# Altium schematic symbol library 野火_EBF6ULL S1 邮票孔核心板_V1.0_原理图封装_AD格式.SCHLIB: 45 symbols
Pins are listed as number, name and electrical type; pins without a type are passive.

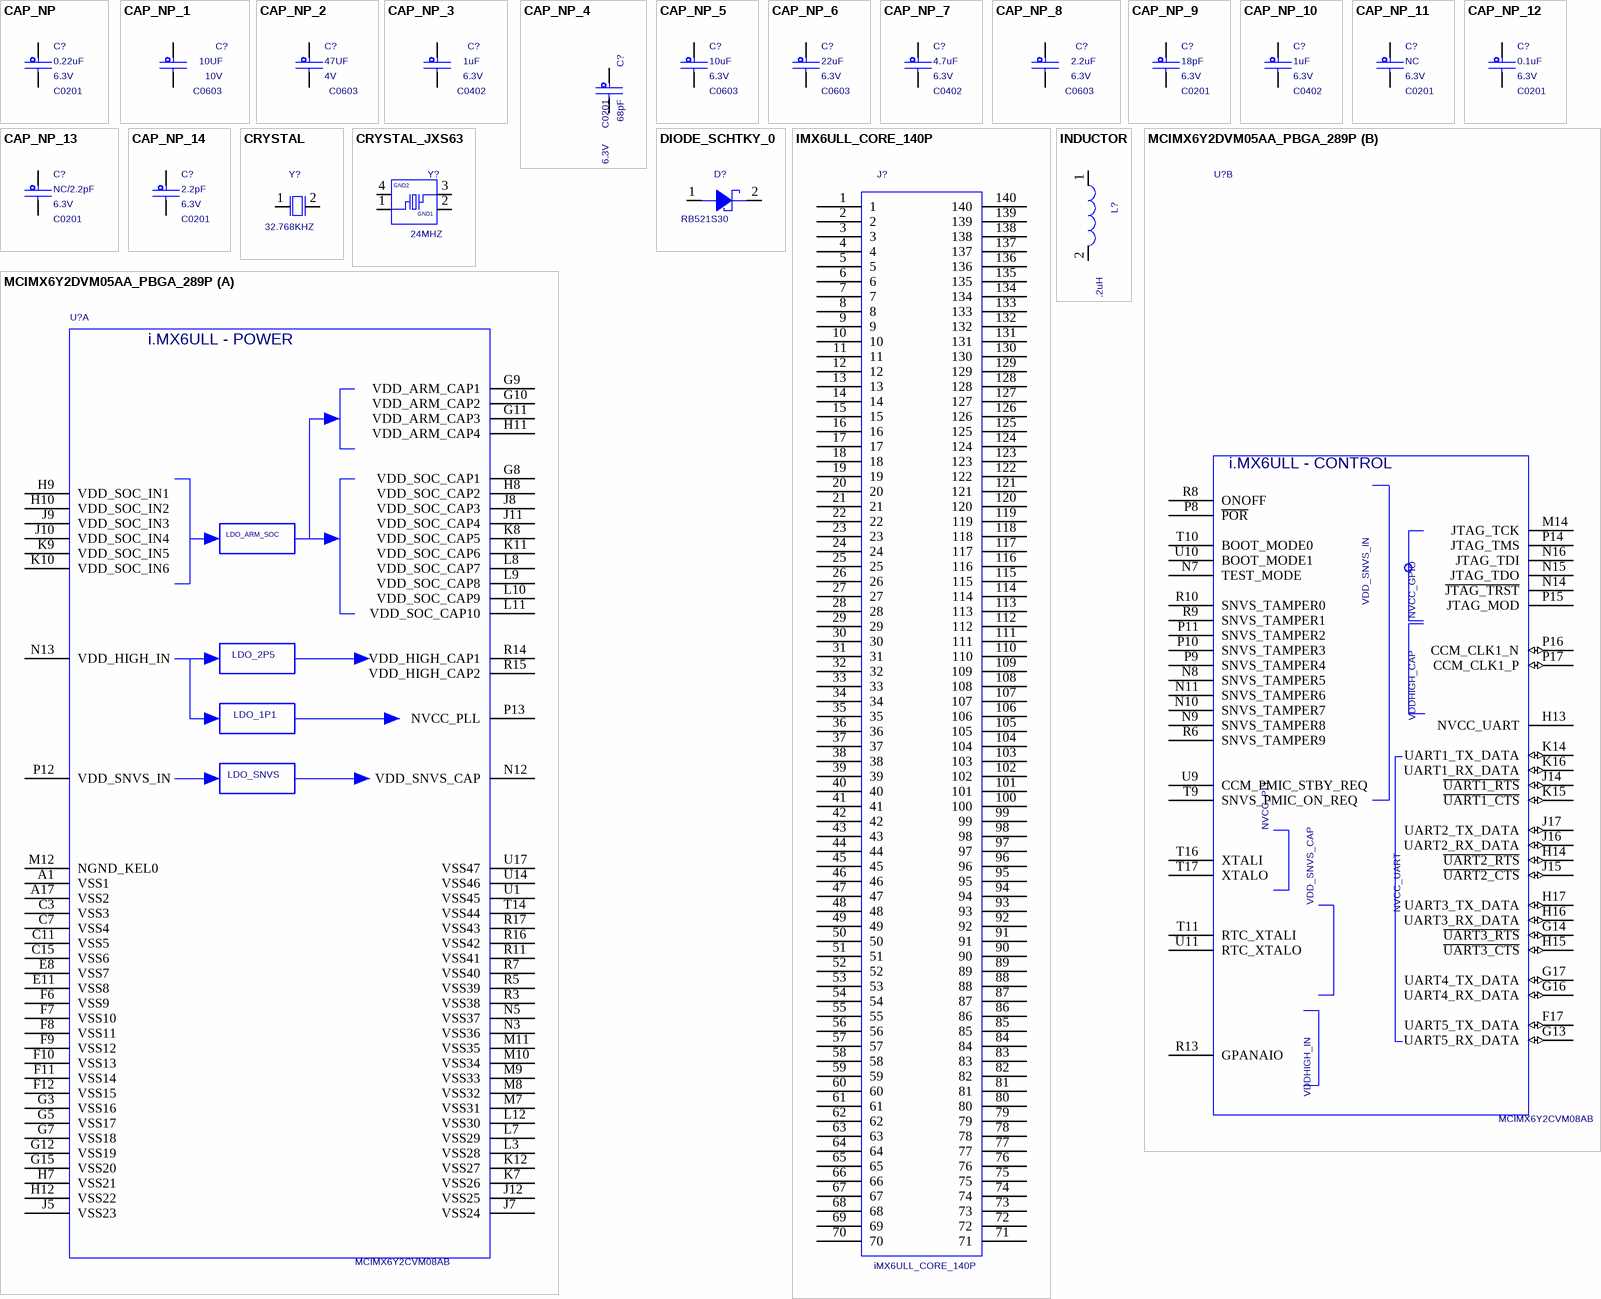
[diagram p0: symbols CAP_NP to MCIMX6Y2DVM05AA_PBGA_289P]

## CAP_NP
designator C?  value 0.22uF  VOLTAGE: 6.3V  PCB DECAL: C0201  (hidden comment: CAP_NP)
CAP CER 0.22UF 6.3V 20% X5R 0402; AGILE_PN: 150-76271; MFG_NAME01: KEMET; MFG_PN01: C0402C224M9PAC; CAD_APPROVED: Yes; FPLIST: CC0402_25,CC0402_HD,0402_CC; Source_Path: Q:\ORCADCIS\SYMBOLS\FCL_CAPACITOR.OLB; CLASS: DISCRETE
footprint C0201
pins: 1, 2

## CAP_NP_1
designator C?, comment value 10UF  PCB DECAL: C0603  voltage_rating: 10V  (hidden comment: CAP_NP)
CAP CER 22UF 6.3V 20% X5R 0603; FPLIST: CC0603_OV,CC0603,0603_CC; CAD_APPROVED: Yes; MFG_PN01: CL10A226MQ8NRNE; MFG_NAME01: Samsung; AGILE_PN: 150-78467; Source_Path: Q:\ORCADCIS\SYMBOLS\FCL_CAPACITOR.OLB; CLASS: DISCRETE
footprint C0603
pins: 1, 2

## CAP_NP_2
designator C?, comment value 47UF  PCB DECAL: C0603  voltage_rating: 4V  (hidden comment: CAP_NP)
CAP CER 22UF 6.3V 20% X5R 0603; AGILE_PN: 150-78467; MFG_NAME01: Samsung; MFG_PN01: CL10A226MQ8NRNE; CAD_APPROVED: Yes; FPLIST: CC0603_OV,CC0603,0603_CC; Source_Path: Q:\ORCADCIS\SYMBOLS\FCL_CAPACITOR.OLB; CLASS: DISCRETE
footprint C0603
pins: 1, 2

## CAP_NP_3
designator C?, comment value 1uF  PCB DECAL: C0402  voltage_rating: 6.3V  (hidden comment: CAP_NP)
CAP CER 22UF 6.3V 20% X5R 0603; FPLIST: CC0603_OV,CC0603,0603_CC; CAD_APPROVED: Yes; MFG_PN01: CL10A226MQ8NRNE; MFG_NAME01: Samsung; AGILE_PN: 150-78467; Source_Path: Q:\ORCADCIS\SYMBOLS\FCL_CAPACITOR.OLB; CLASS: DISCRETE
footprint C0402
pins: 1, 2

## CAP_NP_4
designator C?, comment value 68pF  VOLTAGE: 6.3V  PCB DECAL: C0201  (hidden comment: CAP_NP)
CAP CER 0.22UF 6.3V 20% X5R 0402; FPLIST: CC0402_25,CC0402_HD,0402_CC; CAD_APPROVED: Yes; MFG_PN01: C0402C224M9PAC; MFG_NAME01: KEMET; AGILE_PN: 150-76271; Source_Path: Q:\ORCADCIS\SYMBOLS\FCL_CAPACITOR.OLB; CLASS: DISCRETE
footprint C0201
pins: 1, 2

## CAP_NP_5
designator C?, comment value 10uF  VOLTAGE: 6.3V  PCB DECAL: C0603  (hidden comment: CAP_NP)
CAP CER 0.22UF 6.3V 20% X5R 0402; FPLIST: CC0402_25,CC0402_HD,0402_CC; CAD_APPROVED: Yes; MFG_PN01: C0402C224M9PAC; MFG_NAME01: KEMET; AGILE_PN: 150-76271; Source_Path: Q:\ORCADCIS\SYMBOLS\FCL_CAPACITOR.OLB; CLASS: DISCRETE
footprint C0603
pins: 1, 2

## CAP_NP_6
designator C?, comment value 22uF  VOLTAGE: 6.3V  PCB DECAL: C0603  (hidden comment: CAP_NP)
CAP CER 0.22UF 6.3V 20% X5R 0402; FPLIST: CC0402_25,CC0402_HD,0402_CC; CAD_APPROVED: Yes; MFG_PN01: C0402C224M9PAC; MFG_NAME01: KEMET; AGILE_PN: 150-76271; Source_Path: Q:\ORCADCIS\SYMBOLS\FCL_CAPACITOR.OLB; CLASS: DISCRETE
footprint C0603
pins: 1, 2

## CAP_NP_7
designator C?, comment value 4.7uF  VOLTAGE: 6.3V  PCB DECAL: C0402  (hidden comment: CAP_NP)
CAP CER 0.22UF 6.3V 20% X5R 0402; FPLIST: CC0402_25,CC0402_HD,0402_CC; CAD_APPROVED: Yes; MFG_PN01: C0402C224M9PAC; MFG_NAME01: KEMET; AGILE_PN: 150-76271; Source_Path: Q:\ORCADCIS\SYMBOLS\FCL_CAPACITOR.OLB; CLASS: DISCRETE
footprint C0402
pins: 1, 2

## CAP_NP_8
designator C?, comment value 2.2uF  voltage_rating: 6.3V  PCB DECAL: C0603  (hidden comment: CAP_NP)
CAP CER 22UF 6.3V 20% X5R 0603; AGILE_PN: 150-78467; MFG_NAME01: Samsung; MFG_PN01: CL10A226MQ8NRNE; CAD_APPROVED: Yes; FPLIST: CC0603_OV,CC0603,0603_CC; Source_Path: Q:\ORCADCIS\SYMBOLS\FCL_CAPACITOR.OLB; CLASS: DISCRETE
footprint C0603
pins: 1, 2

## CAP_NP_9
designator C?, comment value 18pF  VOLTAGE: 6.3V  PCB DECAL: C0201  (hidden comment: CAP_NP)
CAP CER 0.22UF 6.3V 20% X5R 0402; AGILE_PN: 150-76271; MFG_NAME01: KEMET; MFG_PN01: C0402C224M9PAC; CAD_APPROVED: Yes; FPLIST: CC0402_25,CC0402_HD,0402_CC; Source_Path: Q:\ORCADCIS\SYMBOLS\FCL_CAPACITOR.OLB; CLASS: DISCRETE
footprint C0201
pins: 1, 2

## CAP_NP_10
designator C?, comment value 1uF  PCB DECAL: C0402  VOLTAGE: 6.3V  (hidden comment: CAP_NP)
CAP CER 0.22UF 6.3V 20% X5R 0402; AGILE_PN: 150-76271; MFG_NAME01: KEMET; MFG_PN01: C0402C224M9PAC; CAD_APPROVED: Yes; FPLIST: CC0402_25,CC0402_HD,0402_CC; Source_Path: Q:\ORCADCIS\SYMBOLS\FCL_CAPACITOR.OLB; CLASS: DISCRETE
footprint C0402
pins: 1, 2

## CAP_NP_11
designator C?, comment value NC  VOLTAGE: 6.3V  PCB DECAL: C0201  (hidden comment: CAP_NP)
CAP CER 0.22UF 6.3V 20% X5R 0402; AGILE_PN: 150-76271; MFG_NAME01: KEMET; MFG_PN01: C0402C224M9PAC; CAD_APPROVED: Yes; FPLIST: CC0402_25,CC0402_HD,0402_CC; Source_Path: Q:\ORCADCIS\SYMBOLS\FCL_CAPACITOR.OLB; CLASS: DISCRETE
footprint C0201
pins: 1, 2

## CAP_NP_12
designator C?, comment value 0.1uF  VOLTAGE: 6.3V  PCB DECAL: C0201  (hidden comment: CAP_NP)
CAP CER 0.22UF 6.3V 20% X5R 0402; FPLIST: CC0402_25,CC0402_HD,0402_CC; CAD_APPROVED: Yes; MFG_PN01: C0402C224M9PAC; MFG_NAME01: KEMET; AGILE_PN: 150-76271; Source_Path: Q:\ORCADCIS\SYMBOLS\FCL_CAPACITOR.OLB; CLASS: DISCRETE
footprint C0201
pins: 1, 2

## CAP_NP_13
designator C?, comment value NC/2.2pF  VOLTAGE: 6.3V  PCB DECAL: C0201  (hidden comment: CAP_NP)
CAP CER 0.22UF 6.3V 20% X5R 0402; FPLIST: CC0402_25,CC0402_HD,0402_CC; CAD_APPROVED: Yes; MFG_PN01: C0402C224M9PAC; MFG_NAME01: KEMET; AGILE_PN: 150-76271; Source_Path: Q:\ORCADCIS\SYMBOLS\FCL_CAPACITOR.OLB; CLASS: DISCRETE
footprint C0201
pins: 1, 2

## CAP_NP_14
designator C?, comment value 2.2pF  VOLTAGE: 6.3V  PCB DECAL: C0201  (hidden comment: CAP_NP)
CAP CER 0.22UF 6.3V 20% X5R 0402; AGILE_PN: 150-76271; MFG_NAME01: KEMET; MFG_PN01: C0402C224M9PAC; CAD_APPROVED: Yes; FPLIST: CC0402_25,CC0402_HD,0402_CC; Source_Path: Q:\ORCADCIS\SYMBOLS\FCL_CAPACITOR.OLB; CLASS: DISCRETE
footprint C0201
pins: 1, 2

## CRYSTAL
designator Y?  value 32.768KHZ  (hidden comment: CRYSTAL)
XTAL 32.768KHZ 7PF 20PPM -- SMT; CAD_APPROVED: Yes; MFG_PN01: FC-135 32.7680KA-AG3; MFG_NAME01: EPSON ELECTRONICS; AGILE_PN: 230-78102; PCB DECAL: 3215; Source_Path: Q:\ORCADCIS\SYMBOLS\FCL_XTAL_OSC.OLB; CLASS: IC
footprint 3215
pins: 1, 2

## CRYSTAL_JXS63
designator Y?  value 24MHZ  (hidden comment: CRYSTAL_JXS63)
XTAL 24MHZ -- 30PPM 3.2X2.5MM SMD; AGILE_PN: 230-77452; MFG_NAME01: TXC CORP; MFG_PN01: 7V24000002; CAD_APPROVED: Yes; PCB DECAL: 3225; Source_Path: Q:\ORCADCIS\SYMBOLS\FCL_XTAL_OSC.OLB; CLASS: IC
footprint 3225
pins: 1, 2 GND1 (power), 3, 4 GND2 (power)

## DIODE_SCHTKY_0
designator D?  value RB521S30  (hidden comment: DIODE_SCHTKY_0)
DIODE SCH RECT 200MA 30V AEC-Q101 SOD-523; CAD_APPROVED: Yes; MFG_PN01: RB521S30,115; MFG_NAME01: NEXPERIA; AGILE_PN: 480-79672; PCB DECAL: SOD523; Source_Path: H:\NXP_RT1050\SCH\IMXRT1052_CORE\CORE\IMXRT1052_1207.DSN; CLASS: IC
footprint SOD523
pins: 1, 2

## IMX6ULL_CORE_140P
designator J?
PCB DECAL: 6ULL_CORE_140P_39X39; Source_Path: C:\MYPROGRAM\CADENCE\SPB_16.6\TOOLS\CAPTURE\LIBRARY\SCH.OLB
footprint 6ULL_CORE_140P_39X39
pins: 1, 2, 3, 4, 5, 6, 7, 8, 9, 10, 11, 12, 13, 14, 15, 16, 17, 18, 19, 20, 21, 22, 23, 24, 25, 26, 27, 28, 29, 30, 31, 32, 33, 34, 35, 36, 37, 38, 39, 40, 41, 42, 43, 44, 45, 46, 47, 48, 49, 50, 51, 52, 53, 54, 55, 56, 57, 58, 59, 60, 61, 62, 63, 64, 65, 66, 67, 68, 69, 70, 71, 72, 73, 74, 75, 76, 77, 78, 79, 80, 81, 82, 83, 84, 85, 86, 87, 88, 89, 90, 91, 92, 93, 94, 95, 96, 97, 98, 99, 100, 101, 102, 103, 104, 105, 106, 107, 108, 109, 110, 111, 112, 113, 114, 115, 116, 117, 118, 119, 120, 121, 122, 123, 124, 125, 126, 127, 128, 129, 130, 131, 132, 133, 134, 135, 136, 137, 138, 139, 140

## INDUCTOR
designator L?  value 2.2uH  (hidden comment: INDUCTOR)
IND WW PWR 1.5uH@1MHZ 2A 20% 2520; PART_TYPE: POWER; PCB DECAL: L2520; CAD_APPROVED: Yes; MFG_PN01: SPH252012H1R5MT; MFG_NAME01: Shenzhen Sunlord Electronics Co., Ltd; AGILE_PN: 180-78270; Source_Path: Q:\ORCADCIS\SYMBOLS\FCL_INDUCTOR.OLB; CLASS: DISCRETE
footprint L2520
pins: 1, 2

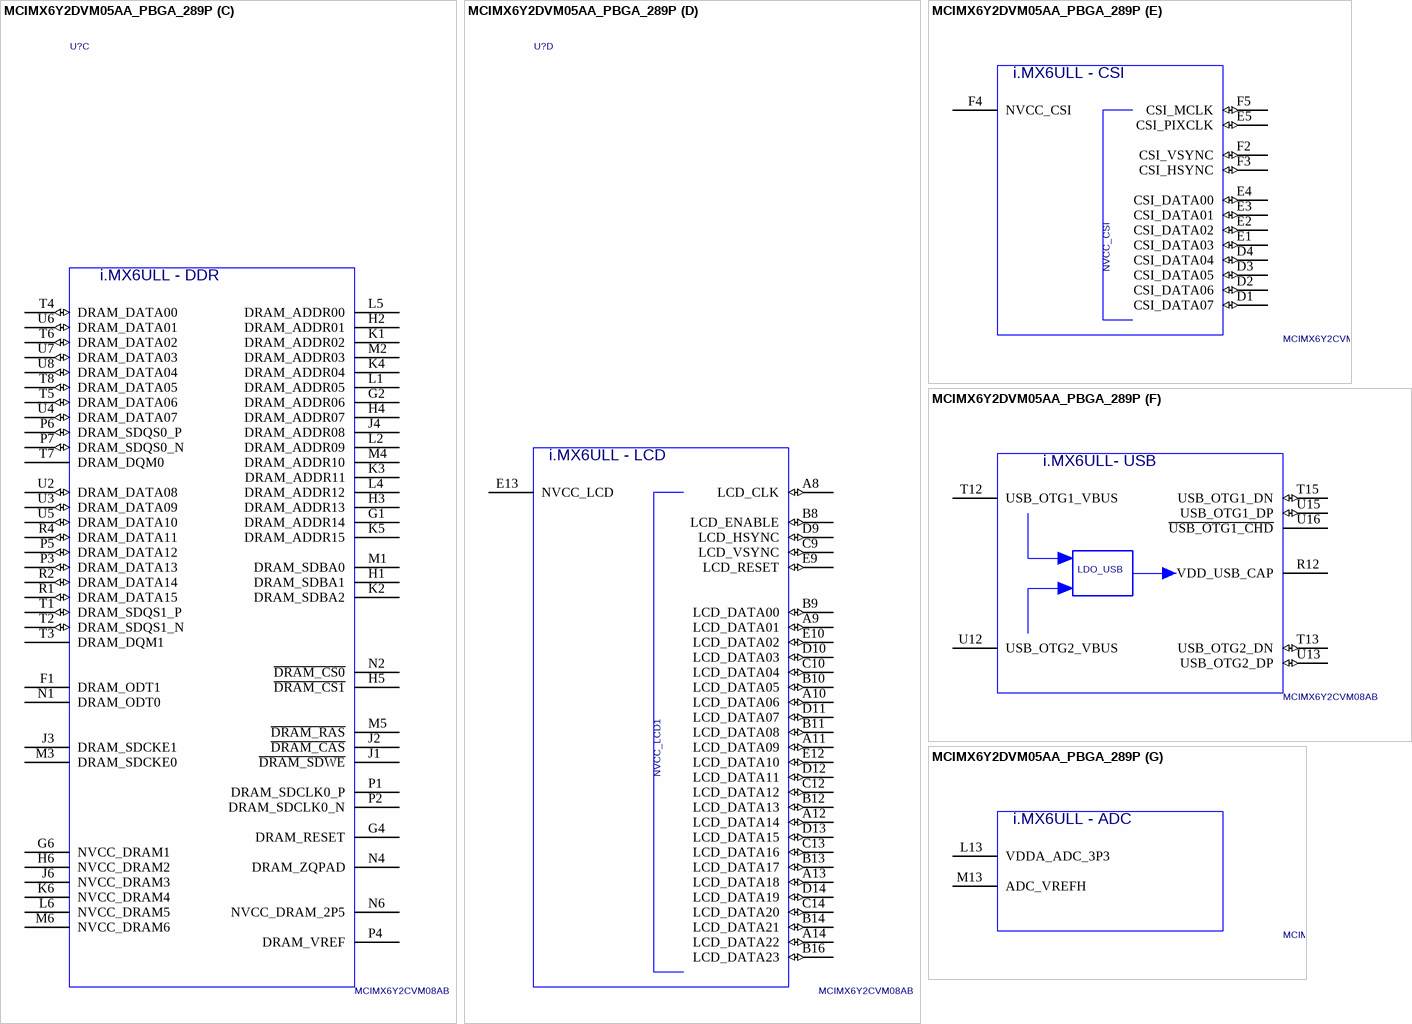
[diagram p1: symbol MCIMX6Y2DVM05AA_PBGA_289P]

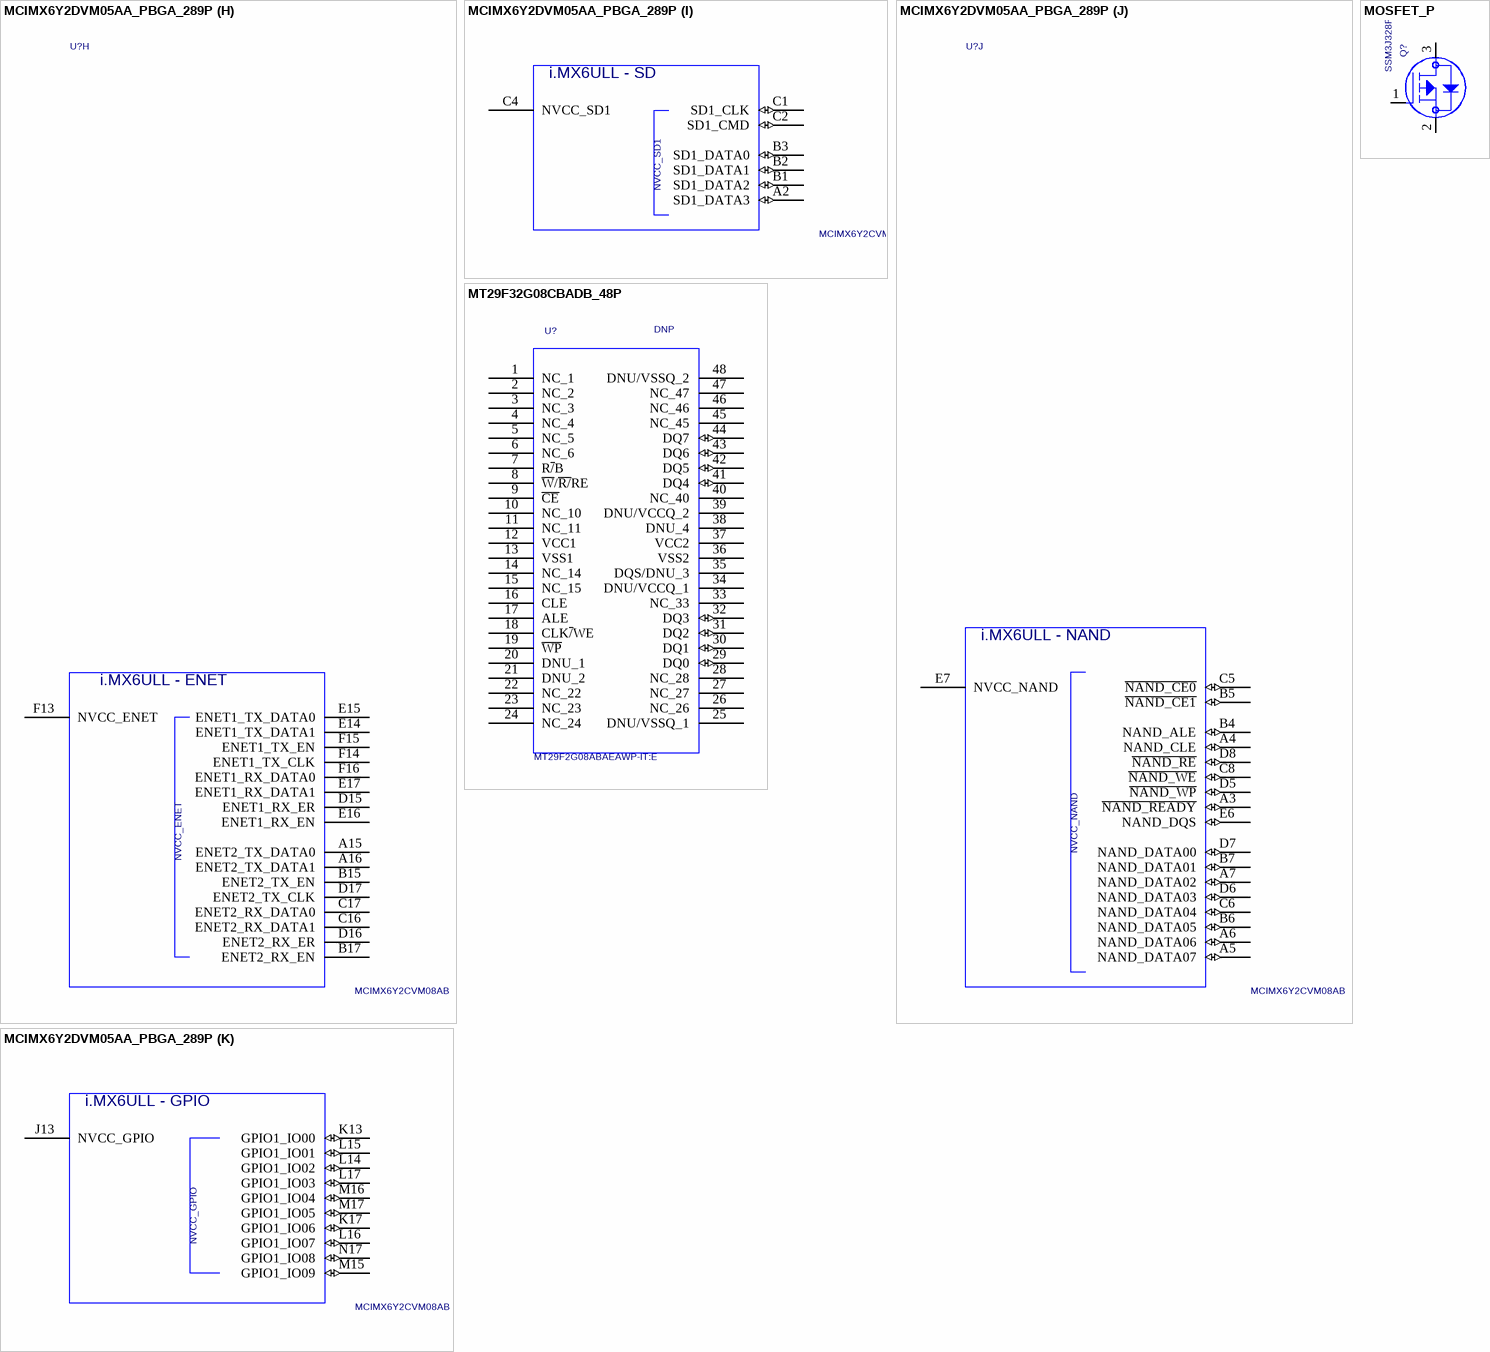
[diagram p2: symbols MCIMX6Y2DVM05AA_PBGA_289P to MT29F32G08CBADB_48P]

## MCIMX6Y2DVM05AA_PBGA_289P
designator U?  value MCIMX6Y2CVM08AB  (hidden comment: MCIMX6Y2DVM05AA_PBGA_289P)
IC CPU ARM COREA7 528MHZ 16BIT 1.5V PBGA289; PCB DECAL: BGA289_0P8_14X14; AGILE_PN: TMP-WF-27909; MFG_NAME01: NXP SEMICONDUCTORS; PRE_APN: 330-77022; CAD_APPROVED: Yes; Source_Path: Q:\ORCADCIS\SYMBOLS\FCL_IC_FREESCALE.OLB
footprint BGA289_0P8_14X14
part A pins: A1 VSS1 (power), A17 VSS2 (power), C3 VSS3 (power), C7 VSS4 (power), C11 VSS5 (power), C15 VSS6 (power), E8 VSS7 (power), E11 VSS8 (power), F6 VSS9 (power), F7 VSS10 (power), F8 VSS11 (power), F9 VSS12 (power), F10 VSS13 (power), F11 VSS14 (power), F12 VSS15 (power), G3 VSS16 (power), G5 VSS17 (power), G7 VSS18 (power), G8 VDD_SOC_CAP1 (power), G9 VDD_ARM_CAP1 (power), G10 VDD_ARM_CAP2 (power), G11 VDD_ARM_CAP3 (power), G12 VSS19 (power), G15 VSS20 (power), H7 VSS21 (power), H8 VDD_SOC_CAP2 (power), H9 VDD_SOC_IN1 (power), H10 VDD_SOC_IN2 (power), H11 VDD_ARM_CAP4 (power), H12 VSS22 (power), J5 VSS23 (power), J7 VSS24 (power), J8 VDD_SOC_CAP3 (power), J9 VDD_SOC_IN3 (power), J10 VDD_SOC_IN4 (power), J11 VDD_SOC_CAP4 (power), J12 VSS25 (power), K7 VSS26 (power), K8 VDD_SOC_CAP5 (power), K9 VDD_SOC_IN5 (power), K10 VDD_SOC_IN6 (power), K11 VDD_SOC_CAP6 (power), K12 VSS27 (power), L3 VSS28 (power), L7 VSS29 (power), L8 VDD_SOC_CAP7 (power), L9 VDD_SOC_CAP8 (power), L10 VDD_SOC_CAP9 (power), L11 VDD_SOC_CAP10 (power), L12 VSS30 (power), M7 VSS31 (power), M8 VSS32 (power), M9 VSS33 (power), M10 VSS34 (power), M11 VSS35 (power), M12 NGND_KEL0 (power), N3 VSS36 (power), N5 VSS37 (power), N12 VDD_SNVS_CAP (power), N13 VDD_HIGH_IN (power), P12 VDD_SNVS_IN (power), P13 NVCC_PLL (power), R3 VSS38 (power), R5 VSS39 (power), R7 VSS40 (power), R11 VSS41 (power), R14 VDD_HIGH_CAP1 (power), R15 VDD_HIGH_CAP2 (power), R16 VSS42 (power), R17 VSS43 (power), T14 VSS44 (power), U1 VSS45 (power), U14 VSS46 (power), U17 VSS47 (power)
part B pins: F17 UART5_TX_DATA (io), G13 UART5_RX_DATA (io), G14 ~{UART3_RTS} (io), G16 UART4_RX_DATA (io), G17 UART4_TX_DATA (io), H13 NVCC_UART, H14 ~{UART2_RTS} (io), H15 ~{UART3_CTS} (io), H16 UART3_RX_DATA (io), H17 UART3_TX_DATA (io), J14 ~{UART1_RTS} (io), J15 ~{UART2_CTS} (io), J16 UART2_RX_DATA (io), J17 UART2_TX_DATA (io), K14 UART1_TX_DATA (io), K15 ~{UART1_CTS} (io), K16 UART1_RX_DATA (io), M14 JTAG_TCK, N7 TEST_MODE, N8 SNVS_TAMPER5, N9 SNVS_TAMPER8, N10 SNVS_TAMPER7, N11 SNVS_TAMPER6, N14 ~{JTAG_TRST}, N15 JTAG_TDO, N16 JTAG_TDI, P8 ~{POR}, P9 SNVS_TAMPER4, P10 SNVS_TAMPER3, P11 SNVS_TAMPER2, P14 JTAG_TMS, P15 JTAG_MOD, P16 CCM_CLK1_N (io), P17 CCM_CLK1_P (io), R6 SNVS_TAMPER9, R8 ONOFF, R9 SNVS_TAMPER1, R10 SNVS_TAMPER0, R13 GPANAIO (power), T9 SNVS_PMIC_ON_REQ, T10 BOOT_MODE0, T11 RTC_XTALI, T16 XTALI, T17 XTALO, U9 CCM_PMIC_STBY_REQ, U10 BOOT_MODE1, U11 RTC_XTALO
part C pins: F1 DRAM_ODT1, G1 DRAM_ADDR14, G2 DRAM_ADDR06, G4 DRAM_RESET, G6 NVCC_DRAM1 (power), H1 DRAM_SDBA1, H2 DRAM_ADDR01, H3 DRAM_ADDR13, H4 DRAM_ADDR07, H5 ~{DRAM_CS1}, H6 NVCC_DRAM2 (power), J1 ~{DRAM_SDWE}, J2 ~{DRAM_CAS}, J3 DRAM_SDCKE1, J4 DRAM_ADDR08, J6 NVCC_DRAM3 (power), K1 DRAM_ADDR02, K2 DRAM_SDBA2, K3 DRAM_ADDR11, K4 DRAM_ADDR04, K5 DRAM_ADDR15, K6 NVCC_DRAM4 (power), L1 DRAM_ADDR05, L2 DRAM_ADDR09, L4 DRAM_ADDR12, L5 DRAM_ADDR00, L6 NVCC_DRAM5 (power), M1 DRAM_SDBA0, M2 DRAM_ADDR03, M3 DRAM_SDCKE0, M4 DRAM_ADDR10, M5 ~{DRAM_RAS}, M6 NVCC_DRAM6 (power), N1 DRAM_ODT0, N2 ~{DRAM_CS0}, N4 DRAM_ZQPAD, N6 NVCC_DRAM_2P5 (power), P1 DRAM_SDCLK0_P, P2 DRAM_SDCLK0_N, P3 DRAM_DATA13 (io), P4 DRAM_VREF (power), P5 DRAM_DATA12 (io), P6 DRAM_SDQS0_P (io), P7 DRAM_SDQS0_N (io), R1 DRAM_DATA15 (io), R2 DRAM_DATA14 (io), R4 DRAM_DATA11 (io), T1 DRAM_SDQS1_P (io), T2 DRAM_SDQS1_N (io), T3 DRAM_DQM1, T4 DRAM_DATA00 (io), T5 DRAM_DATA06 (io), T6 DRAM_DATA02 (io), T7 DRAM_DQM0, T8 DRAM_DATA05 (io), U2 DRAM_DATA08 (io), U3 DRAM_DATA09 (io), U4 DRAM_DATA07 (io), U5 DRAM_DATA10 (io), U6 DRAM_DATA01 (io), U7 DRAM_DATA03 (io), U8 DRAM_DATA04 (io)
part D pins: A8 LCD_CLK (io), A9 LCD_DATA01 (io), A10 LCD_DATA06 (io), A11 LCD_DATA09 (io), A12 LCD_DATA14 (io), A13 LCD_DATA18 (io), A14 LCD_DATA22 (io), B8 LCD_ENABLE (io), B9 LCD_DATA00 (io), B10 LCD_DATA05 (io), B11 LCD_DATA08 (io), B12 LCD_DATA13 (io), B13 LCD_DATA17 (io), B14 LCD_DATA21 (io), B16 LCD_DATA23 (io), C9 LCD_VSYNC (io), C10 LCD_DATA04 (io), C12 LCD_DATA12 (io), C13 LCD_DATA16 (io), C14 LCD_DATA20 (io), D9 LCD_HSYNC (io), D10 LCD_DATA03 (io), D11 LCD_DATA07 (io), D12 LCD_DATA11 (io), D13 LCD_DATA15 (io), D14 LCD_DATA19 (io), E9 LCD_RESET (io), E10 LCD_DATA02 (io), E12 LCD_DATA10 (io), E13 NVCC_LCD (power)
part E pins: D1 CSI_DATA07 (io), D2 CSI_DATA06 (io), D3 CSI_DATA05 (io), D4 CSI_DATA04 (io), E1 CSI_DATA03 (io), E2 CSI_DATA02 (io), E3 CSI_DATA01 (io), E4 CSI_DATA00 (io), E5 CSI_PIXCLK (io), F2 CSI_VSYNC (io), F3 CSI_HSYNC (io), F4 NVCC_CSI (power), F5 CSI_MCLK (io)
part F pins: R12 VDD_USB_CAP (power), T12 USB_OTG1_VBUS (power), T13 USB_OTG2_DN (io), T15 USB_OTG1_DN (io), U12 USB_OTG2_VBUS (power), U13 USB_OTG2_DP (io), U15 USB_OTG1_DP (io), U16 ~{USB_OTG1_CHD}
part G pins: L13 VDDA_ADC_3P3 (power), M13 ADC_VREFH (power)
part H pins: A15 ENET2_TX_DATA0, A16 ENET2_TX_DATA1, B15 ENET2_TX_EN, B17 ENET2_RX_EN, C16 ENET2_RX_DATA1, C17 ENET2_RX_DATA0, D15 ENET1_RX_ER, D16 ENET2_RX_ER, D17 ENET2_TX_CLK, E14 ENET1_TX_DATA1, E15 ENET1_TX_DATA0, E16 ENET1_RX_EN, E17 ENET1_RX_DATA1, F13 NVCC_ENET (power), F14 ENET1_TX_CLK, F15 ENET1_TX_EN, F16 ENET1_RX_DATA0
part I pins: A2 SD1_DATA3 (io), B1 SD1_DATA2 (io), B2 SD1_DATA1 (io), B3 SD1_DATA0 (io), C1 SD1_CLK (io), C2 SD1_CMD (io), C4 NVCC_SD1 (power)
part J pins: A3 ~{NAND_READY} (io), A4 NAND_CLE (io), A5 NAND_DATA07 (io), A6 NAND_DATA06 (io), A7 NAND_DATA02 (io), B4 NAND_ALE (io), B5 ~{NAND_CE1} (io), B6 NAND_DATA05 (io), B7 NAND_DATA01 (io), C5 ~{NAND_CE0} (io), C6 NAND_DATA04 (io), C8 ~{NAND_WE} (io), D5 ~{NAND_WP} (io), D6 NAND_DATA03 (io), D7 NAND_DATA00 (io), D8 ~{NAND_RE} (io), E6 NAND_DQS (io), E7 NVCC_NAND (power)
part K pins: J13 NVCC_GPIO (power), K13 GPIO1_IO00 (io), K17 GPIO1_IO06 (io), L14 GPIO1_IO02 (io), L15 GPIO1_IO01 (io), L16 GPIO1_IO07 (io), L17 GPIO1_IO03 (io), M15 GPIO1_IO09 (io), M16 GPIO1_IO04 (io), M17 GPIO1_IO05 (io), N17 GPIO1_IO08 (io)

## MOSFET_P
designator Q?  value SSM3J328R  (hidden comment: MOSFET_P)
TRAN PMOS PWR 12V 4.3A SOT23; CAD_APPROVED: Yes; MFG_PN01: IRLML6401TRPBF; MFG_NAME01: INTERNATIONAL RECTIFIER; AGILE_PN: 480-77718; Source_Path: Q:\ORCADCIS\SYMBOLS\FCL_SEMICONDUCTOR.OLB; CLASS: IC
footprint SOT23
pins: 1 GATE, 2 SOURCE, 3 DRAIN

## MT29F32G08CBADB_48P
designator U?  value MT29F2G08ABAEAWP-IT:E  ASSY_OPT: DNP  (hidden comment: MT29F32G08CBADB_48P)
IC MEM NAND FLASH ASYNC 32GB 2.7-3.6V TSOP48; PCB DECAL: TSOP48-050-1220; CAD_APPROVED: Yes; MFG_PN01: MT29F32G08CBADBWP-12IT:D; MFG_NAME01: Micron; AGILE_PN: 334-77617; Source_Path: Q:\ORCADCIS\SYMBOLS\FCL_IC3.OLB
footprint TSOP48-050-1220
pins: 1 NC_1, 2 NC_2, 3 NC_3, 4 NC_4, 5 NC_5, 6 NC_6, 7 R~{/}B (oc), 8 ~{W}/~{R/}RE, 9 ~{CE}, 10 NC_10, 11 NC_11, 12 VCC1 (power), 13 VSS1 (power), 14 NC_14, 15 NC_15, 16 CLE, 17 ALE, 18 CLK~{/}WE, 19 ~{WP}, 20 DNU_1, 21 DNU_2, 22 NC_22, 23 NC_23, 24 NC_24, 25 DNU/VSSQ_1 (power), 26 NC_26, 27 NC_27, 28 NC_28, 29 DQ0 (io), 30 DQ1 (io), 31 DQ2 (io), 32 DQ3 (io), 33 NC_33, 34 DNU/VCCQ_1 (power), 35 DQS/DNU_3, 36 VSS2 (power), 37 VCC2 (power), 38 DNU_4, 39 DNU/VCCQ_2, 40 NC_40, 41 DQ4 (io), 42 DQ5 (io), 43 DQ6 (io), 44 DQ7 (io), 45 NC_45, 46 NC_46, 47 NC_47, 48 DNU/VSSQ_2 (power)

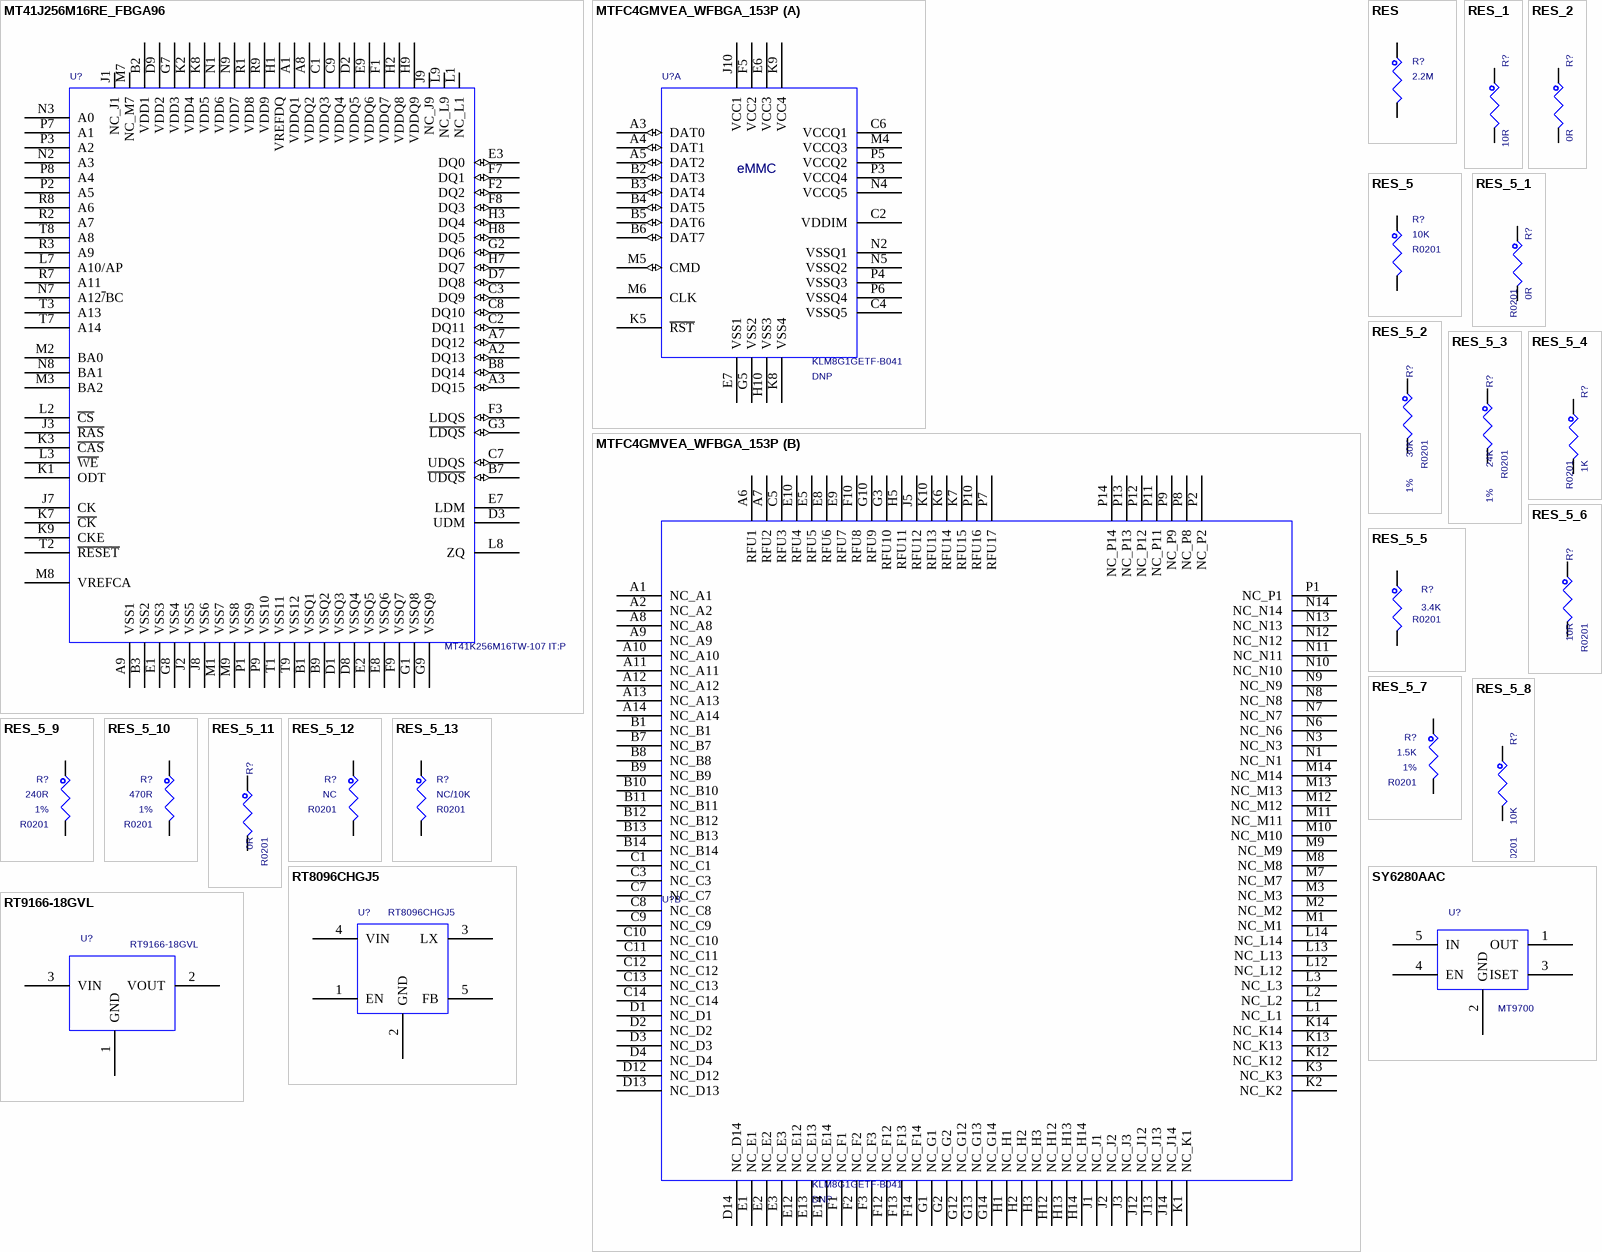
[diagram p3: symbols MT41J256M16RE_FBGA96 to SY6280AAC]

## MT41J256M16RE_FBGA96
designator U?  value MT41K256M16TW-107 IT:P  (hidden comment: MT41J256M16RE_FBGA96)
IC MEM DDR3 SDRAM 256MX16 1.071NS 1.35V FBGA96; PCB DECAL: BGA96_0P8_8P15X14P15; CAD_APPROVED: Yes; MFG_PN01: MT41K256M16TW-107:P; MFG_NAME01: MICRON; AGILE_PN: 334-77510; Source_Path: Q:\ORCADCIS\SYMBOLS\FCL_IC5.OLB
footprint BGA96_0P8_8P15X14P15
pins: A1 VDDQ1 (power), A2 DQ13 (io), A3 DQ15 (io), A7 DQ12 (io), A8 VDDQ2 (power), A9 VSS1 (power), B1 VSSQ1 (power), B2 VDD1 (power), B3 VSS2 (power), B7 ~{UDQS} (io), B8 DQ14 (io), B9 VSSQ2 (power), C1 VDDQ3 (power), C2 DQ11 (io), C3 DQ9 (io), C7 UDQS (io), C8 DQ10 (io), C9 VDDQ4 (power), D1 VSSQ3 (power), D2 VDDQ5 (power), D3 UDM, D7 DQ8 (io), D8 VSSQ4 (power), D9 VDD2 (power), E1 VSS3 (power), E2 VSSQ5 (power), E3 DQ0 (io), E7 LDM, E8 VSSQ6 (power), E9 VDDQ6 (power), F1 VDDQ7 (power), F2 DQ2 (io), F3 LDQS (io), F7 DQ1 (io), F8 DQ3 (io), F9 VSSQ7 (power), G1 VSSQ8 (power), G2 DQ6 (io), G3 ~{LDQS} (io), G7 VDD3 (power), G8 VSS4 (power), G9 VSSQ9 (power), H1 VREFDQ, H2 VDDQ8 (power), H3 DQ4 (io), H7 DQ7 (io), H8 DQ5 (io), H9 VDDQ9 (power), J1 NC_J1, J2 VSS5 (power), J3 ~{RAS}, J7 CK, J8 VSS6 (power), J9 NC_J9, K1 ODT, K2 VDD4 (power), K3 ~{CAS}, K7 ~{CK}, K8 VDD5 (power), K9 CKE, L1 NC_L1, L2 ~{CS}, L3 ~{WE}, L7 A10/AP, L8 ZQ, L9 NC_L9, M1 VSS7 (power), M2 BA0, M3 BA2, M7 NC_M7, M8 VREFCA, M9 VSS8 (power), N1 VDD6 (power), N2 A3, N3 A0, N7 A12~{/}BC, N8 BA1, N9 VDD7 (power), P1 VSS9 (power), P2 A5, P3 A2, P7 A1, P8 A4, P9 VSS10 (power), R1 VDD8 (power), R2 A7, R3 A9, R7 A11, R8 A6, R9 VDD9 (power), T1 VSS11 (power), T2 ~{RESET}, T3 A13, T7 A14, T8 A8, T9 VSS12 (power)

## MTFC4GMVEA_WFBGA_153P
designator U?  value KLM8G1GETF-B041  ASSY_OPT: DNP  (hidden comment: MTFC4GMVEA_WFBGA_153P)
IC MEM NAND FLASH 8GB MMC 4.51 CTLR 2.7-3.6V FBGA153; PCB DECAL: FBGA153_0P5_11P5X13; CAD_APPROVED: Yes; MFG_PN01: MTFC8GACAAAM-1M WT; MFG_NAME01: MICRON; AGILE_PN: 342-00603; Source_Path: Q:\ORCADCIS\SYMBOLS\FCL_IC5.OLB
footprint FBGA153_0P5_11P5X13
part A pins: A3 DAT0 (io), A4 DAT1 (io), A5 DAT2 (io), B2 DAT3 (io), B3 DAT4 (io), B4 DAT5 (io), B5 DAT6 (io), B6 DAT7 (io), C2 VDDIM (power), C4 VSSQ5 (power), C6 VCCQ1 (power), E6 VCC3 (power), E7 VSS1 (power), F5 VCC2 (power), G5 VSS2 (power), H10 VSS3 (power), J10 VCC1 (power), K5 ~{RST}, K8 VSS4 (power), K9 VCC4 (power), M4 VCCQ3 (power), M5 CMD (io), M6 CLK, N2 VSSQ1 (power), N4 VCCQ5 (power), N5 VSSQ2 (power), P3 VCCQ4 (power), P4 VSSQ3 (power), P5 VCCQ2 (power), P6 VSSQ4 (power)
part B pins: A1 NC_A1, A2 NC_A2, A6 RFU1, A7 RFU2, A8 NC_A8, A9 NC_A9, A10 NC_A10, A11 NC_A11, A12 NC_A12, A13 NC_A13, A14 NC_A14, B1 NC_B1, B7 NC_B7, B8 NC_B8, B9 NC_B9, B10 NC_B10, B11 NC_B11, B12 NC_B12, B13 NC_B13, B14 NC_B14, C1 NC_C1, C3 NC_C3, C5 RFU3, C7 NC_C7, C8 NC_C8, C9 NC_C9, C10 NC_C10, C11 NC_C11, C12 NC_C12, C13 NC_C13, C14 NC_C14, D1 NC_D1, D2 NC_D2, D3 NC_D3, D4 NC_D4, D12 NC_D12, D13 NC_D13, D14 NC_D14, E1 NC_E1, E2 NC_E2, E3 NC_E3, E5 RFU5, E8 RFU6, E9 RFU7, E10 RFU4, E12 NC_E12, E13 NC_E13, E14 NC_E14, F1 NC_F1, F2 NC_F2, F3 NC_F3, F10 RFU8, F12 NC_F12, F13 NC_F13, F14 NC_F14, G1 NC_G1, G2 NC_G2, G3 RFU10, G10 RFU9, G12 NC_G12, G13 NC_G13, G14 NC_G14, H1 NC_H1, H2 NC_H2, H3 NC_H3, H5 RFU11, H12 NC_H12, H13 NC_H13, H14 NC_H14, J1 NC_J1, J2 NC_J2, J3 NC_J3, J5 RFU12, J12 NC_J12, J13 NC_J13, J14 NC_J14, K1 NC_K1, K2 NC_K2, K3 NC_K3, K6 RFU14, K7 RFU15, K10 RFU13, K12 NC_K12, K13 NC_K13, K14 NC_K14, L1 NC_L1, L2 NC_L2, L3 NC_L3, L12 NC_L12, L13 NC_L13, L14 NC_L14, M1 NC_M1, M2 NC_M2, M3 NC_M3, M7 NC_M7, M8 NC_M8, M9 NC_M9, M10 NC_M10, M11 NC_M11, M12 NC_M12, M13 NC_M13, M14 NC_M14, N1 NC_N1, N3 NC_N3, N6 NC_N6, N7 NC_N7, N8 NC_N8, N9 NC_N9, N10 NC_N10, N11 NC_N11, N12 NC_N12, N13 NC_N13, N14 NC_N14, P1 NC_P1, P2 NC_P2, P7 RFU17, P8 NC_P8, P9 NC_P9, P10 RFU16, P11 NC_P11, P12 NC_P12, P13 NC_P13, P14 NC_P14

## RES
designator R?  value 2.2M  (hidden comment: RES)
RES MF 2.2M  1/16W 1% 0402; AGILE_PN: 470-31210; MFG_NAME01: KOA SPEER; MFG_PN01: RK73H1ETTP2204F; CAD_APPROVED: Yes; FPLIST: RC0402_25,RC0402_HD,0402_CC; PCB DECAL: R0201; Source_Path: Q:\ORCADCIS\SYMBOLS\FCL_RESISTOR.OLB; CLASS: DISCRETE
footprint R0201
pins: 1, 2

## RES_1
designator R?, comment value 10R  (hidden comment: RES)
RES MF 10 OHM 1/16W 5% 0402; PCB DECAL: R0201; FPLIST: RC0402_25,RC0402_HD,0402_CC; CAD_APPROVED: Yes; MFG_PN01: CR0402-16W-100JT; MFG_NAME01: VENKEL COMPANY; AGILE_PN: 470-75589; Source_Path: Q:\ORCADCIS\SYMBOLS\FCL_RESISTOR.OLB; CLASS: DISCRETE
footprint R0201
pins: 1, 2

## RES_2
designator R?, comment value 0R  (hidden comment: RES)
RES MF ZERO OHM 1/16W 5% 0402; PCB DECAL: R0201; AGILE_PN: 470-75394; MFG_NAME01: ROHM; MFG_PN01: MCR01MZPJ000; CAD_APPROVED: Yes; FPLIST: RC0402_25,RC0402_HD,RC0402_X2,0402_CC; Source_Path: Q:\ORCADCIS\SYMBOLS\FCL_RESISTOR.OLB; CLASS: DISCRETE
footprint R0201
pins: 1, 2

## RES_5
designator R?  value 10K  PCB DECAL: R0201  (hidden comment: RES_5)
RES MF 180K 1/10W 1% AEC-Q200 0402; Temp_Range: -55C to +155C; FPLIST: RC0402_25,RC0402_HD,0402_CC; CAD_APPROVED: Yes; MFG_PN01: RK73H1ETTP1803F; MFG_NAME01: KOA SPEER; AGILE_PN: 470-31088; Source_Path: F:\NXP\RT1020\SCH\IMXRT1021_0928_1.DSN; CLASS: DISCRETE
footprint R0201
pins: 1, 2

## RES_5_1
designator R?, comment value 0R  PCB DECAL: R0201  (hidden comment: RES_5)
RES MF ZERO OHM 1/16W 5% 0402; AGILE_PN: 470-75394; MFG_NAME01: ROHM; MFG_PN01: MCR01MZPJ000; CAD_APPROVED: Yes; FPLIST: RC0402_25,RC0402_HD,RC0402_X2,0402_CC; Source_Path: F:\NXP\RT1020\SCH\IMXRT1021_0928_1.DSN; CLASS: DISCRETE
footprint R0201
pins: 1, 2

## RES_5_2
designator R?, comment value 30K  PCB DECAL: R0201  Tolerance: 1%  (hidden comment: RES_5)
RES MF 180K 1/10W 1% AEC-Q200 0402; AGILE_PN: 470-31088; MFG_NAME01: KOA SPEER; MFG_PN01: RK73H1ETTP1803F; CAD_APPROVED: Yes; FPLIST: RC0402_25,RC0402_HD,0402_CC; Temp_Range: -55C to +155C; Source_Path: F:\NXP\RT1020\SCH\IMXRT1021_0928_1.DSN; CLASS: DISCRETE
footprint R0201
pins: 1, 2

## RES_5_3
designator R?, comment value 24K  PCB DECAL: R0201  Tolerance: 1%  (hidden comment: RES_5)
RES MF 180K 1/10W 1% AEC-Q200 0402; AGILE_PN: 470-31088; MFG_NAME01: KOA SPEER; MFG_PN01: RK73H1ETTP1803F; CAD_APPROVED: Yes; FPLIST: RC0402_25,RC0402_HD,0402_CC; Temp_Range: -55C to +155C; Source_Path: F:\NXP\RT1020\SCH\IMXRT1021_0928_1.DSN; CLASS: DISCRETE
footprint R0201
pins: 1, 2

## RES_5_4
designator R?, comment value 1K  PCB DECAL: R0201  (hidden comment: RES_5)
RES MF ZERO OHM 1/16W 5% 0402; AGILE_PN: 470-75394; MFG_NAME01: ROHM; MFG_PN01: MCR01MZPJ000; CAD_APPROVED: Yes; FPLIST: RC0402_25,RC0402_HD,RC0402_X2,0402_CC; Source_Path: F:\NXP\RT1020\SCH\IMXRT1021_0928_1.DSN; CLASS: DISCRETE
footprint R0201
pins: 1, 2

## RES_5_5
designator R?, comment value 3.4K  PCB DECAL: R0201  (hidden comment: RES_5)
RES MF 180K 1/10W 1% AEC-Q200 0402; Temp_Range: -55C to +155C; FPLIST: RC0402_25,RC0402_HD,0402_CC; CAD_APPROVED: Yes; MFG_PN01: RK73H1ETTP1803F; MFG_NAME01: KOA SPEER; AGILE_PN: 470-31088; Source_Path: F:\NXP\RT1020\SCH\IMXRT1021_0928_1.DSN; CLASS: DISCRETE
footprint R0201
pins: 1, 2

## RES_5_6
designator R?, comment value 10R  PCB DECAL: R0201  (hidden comment: RES_5)
RES MF 180K 1/10W 1% AEC-Q200 0402; AGILE_PN: 470-31088; MFG_NAME01: KOA SPEER; MFG_PN01: RK73H1ETTP1803F; CAD_APPROVED: Yes; FPLIST: RC0402_25,RC0402_HD,0402_CC; Temp_Range: -55C to +155C; Source_Path: F:\NXP\RT1020\SCH\IMXRT1021_0928_1.DSN; CLASS: DISCRETE
footprint R0201
pins: 1, 2

## RES_5_7
designator R?, comment value 1.5K  Tolerance: 1%  PCB DECAL: R0201  (hidden comment: RES_5)
RES MF 180K 1/10W 1% AEC-Q200 0402; Temp_Range: -55C to +155C; FPLIST: RC0402_25,RC0402_HD,0402_CC; CAD_APPROVED: Yes; MFG_PN01: RK73H1ETTP1803F; MFG_NAME01: KOA SPEER; AGILE_PN: 470-31088; Source_Path: F:\NXP\RT1020\SCH\IMXRT1021_0928_1.DSN; CLASS: DISCRETE
footprint R0201
pins: 1, 2

## RES_5_8
designator R?, comment value 10K  PCB DECAL: R0201  (hidden comment: RES_5)
RES MF 10K 1/16W 5% 0402; FPLIST: RC0402_25,RC0402_HD,0402_CC; CAD_APPROVED: Yes; MFG_PN01: CRCW040210K0JNED; MFG_NAME01: VISHAY INTERTECHNOLOGY; AGILE_PN: 470-75557; Source_Path: F:\NXP\RT1020\SCH\IMXRT1021_0928_1.DSN; CLASS: DISCRETE
footprint R0201
pins: 1, 2

## RES_5_9
designator R?, comment value 240R  Tolerance: 1%  PCB DECAL: R0201  (hidden comment: RES_5)
RES MF 180K 1/10W 1% AEC-Q200 0402; AGILE_PN: 470-31088; MFG_NAME01: KOA SPEER; MFG_PN01: RK73H1ETTP1803F; CAD_APPROVED: Yes; FPLIST: RC0402_25,RC0402_HD,0402_CC; Temp_Range: -55C to +155C; Source_Path: F:\NXP\RT1020\SCH\IMXRT1021_0928_1.DSN; CLASS: DISCRETE
footprint R0201
pins: 1, 2

## RES_5_10
designator R?, comment value 470R  Tolerance: 1%  PCB DECAL: R0201  (hidden comment: RES_5)
RES MF 180K 1/10W 1% AEC-Q200 0402; Temp_Range: -55C to +155C; FPLIST: RC0402_25,RC0402_HD,0402_CC; CAD_APPROVED: Yes; MFG_PN01: RK73H1ETTP1803F; MFG_NAME01: KOA SPEER; AGILE_PN: 470-31088; Source_Path: F:\NXP\RT1020\SCH\IMXRT1021_0928_1.DSN; CLASS: DISCRETE
footprint R0201
pins: 1, 2

## RES_5_11
designator R?, comment value 0R  PCB DECAL: R0201  (hidden comment: RES_5)
RES MF 180K 1/10W 1% AEC-Q200 0402; AGILE_PN: 470-31088; MFG_NAME01: KOA SPEER; MFG_PN01: RK73H1ETTP1803F; CAD_APPROVED: Yes; FPLIST: RC0402_25,RC0402_HD,0402_CC; Temp_Range: -55C to +155C; Source_Path: F:\NXP\RT1020\SCH\IMXRT1021_0928_1.DSN; CLASS: DISCRETE
footprint R0201
pins: 1, 2

## RES_5_12
designator R?, comment value NC  PCB DECAL: R0201  (hidden comment: RES_5)
RES MF 180K 1/10W 1% AEC-Q200 0402; AGILE_PN: 470-31088; MFG_NAME01: KOA SPEER; MFG_PN01: RK73H1ETTP1803F; CAD_APPROVED: Yes; FPLIST: RC0402_25,RC0402_HD,0402_CC; Temp_Range: -55C to +155C; Source_Path: F:\NXP\RT1020\SCH\IMXRT1021_0928_1.DSN; CLASS: DISCRETE
footprint R0201
pins: 1, 2

## RES_5_13
designator R?, comment value NC/10K  PCB DECAL: R0201  (hidden comment: RES_5)
RES MF 10K 1/16W 5% 0402; AGILE_PN: 470-75557; MFG_NAME01: VISHAY INTERTECHNOLOGY; MFG_PN01: CRCW040210K0JNED; CAD_APPROVED: Yes; FPLIST: RC0402_25,RC0402_HD,0402_CC; Source_Path: F:\NXP\RT1020\SCH\IMXRT1021_0928_1.DSN; CLASS: DISCRETE
footprint R0201
pins: 1, 2

## RT8096CHGJ5
designator U?
PCB DECAL: TSOT-23-5; Source_Path: F:\SCH-PCB\EBF_L001\SCH\LIBRARY1.OLB
footprint TSOT-23-5
pins: 1 EN, 2 GND, 3 LX, 4 VIN, 5 FB

## RT9166-18GVL
designator U?
PCB DECAL: SOT23; Source_Path: F:\SCH-PCB\EBF_L003\SCH\SCH.OLB
footprint SOT23
pins: 1 GND, 2 VOUT, 3 VIN

## SY6280AAC
designator U?  value MT9700  (hidden comment: SY6280AAC)
PCB DECAL: SOT23-5; Source_Path: G:\开发板代码\郭老师资料\IMX6资料\原理图\SABRESDB_DESIGNFILES\DEVELOP\LIBRARY1.OLB
footprint SOT23-5
pins: 1 OUT, 2 GND, 3 ISET, 4 EN, 5 IN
